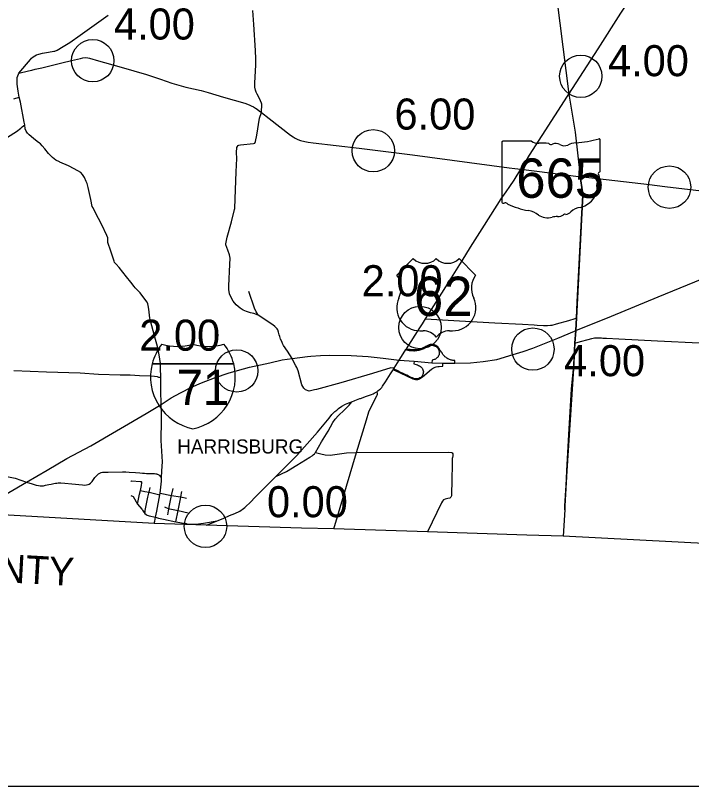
# Model space of a CAD drawing. Extents: x 1729596 to 1934326, y 644115 to 911751.
# Drawn here: x 1774831 to 1798753, y 650175 to 677476 of the extents above; entities that cross this region are included whole.
import ezdxf

# ---------------------------------------------------------------- set-up
doc = ezdxf.new("R2010")
doc.units = 0
for name, color, linetype in [('Default', 7, 'Continuous'), ('GM_X_Adjacent_County_Text', 7, 'Continuous'), ('GM_X_City_Street', 7, 'Continuous'), ('GM_X_Corporation_Text', 7, 'Continuous'), ('GM_X_County', 7, 'Continuous'), ('GM_X_County_Road', 7, 'Continuous'), ('GM_X_Interchange_Ramps', 7, 'Continuous'), ('GM_X_Interstate_Route', 7, 'Continuous'), ('GM_X_Interstate_Shield', 7, 'Continuous'), ('GM_X_State_Route', 7, 'Continuous'), ('GM_X_State_Shield', 7, 'Continuous'), ('GM_X_Township', 7, 'Continuous'), ('GM_X_Township_Road', 7, 'Continuous'), ('GM_X_US_Route', 7, 'Continuous'), ('GM_X_US_Shield', 7, 'Continuous'), ('SC_Scratch1', 7, 'Continuous')]:
    doc.layers.add(name, color=color, linetype=linetype)

msp = doc.modelspace()

# ---------------------------------------------------------------- linework, layer by layer
at = {"layer": 'Default'}
for centre in [(1777567, 675872), (1794833, 675322), (1787491, 672684), (1797971, 671396), (1789142, 666427), (1793139, 665662), (1782661, 664892), (1781555, 659388), (1781555, 659388)]:
    msp.add_circle(centre, 750, dxfattribs=at)
at = {"layer": 'GM_X_City_Street'}
for points in [[(1779847, 661240), (1779853, 661239), (1779883, 661223), (1779909, 661206), (1779930, 661187), (1779979, 661133), (1780000, 661107)], [(1778915, 660978), (1778930, 660991), (1778950, 660994), (1779248, 660981), (1779262, 660981), (1779284, 660976)], [(1779263, 660711), (1779287, 660836), (1779305, 660926), (1779302, 660952), (1779284, 660976)], [(1779741, 659492), (1779762, 659575), (1779789, 659710), (1779832, 659924), (1779945, 660504), (1779955, 660564), (1779994, 660984), (1779997, 661054)], [(1779147, 660174), (1779218, 660526), (1779253, 660654), (1779263, 660711)], [(1779551, 660558), (1779561, 660595), (1779563, 660601), (1779594, 660760)], [(1780218, 659794), (1780262, 660012), (1780354, 660480), (1780407, 660730)], [(1778914, 660484), (1778995, 660444), (1779147, 660174), (1779301, 659998), (1779316, 659981)], [(1779253, 660654), (1779413, 660623)], [(1779413, 660623), (1779561, 660595), (1779945, 660504)], [(1779413, 659848), (1779419, 659887), (1779421, 659949), (1779516, 660426), (1779551, 660558)], [(1779955, 660564), (1780354, 660480), (1780676, 660432)], [(1780676, 660432), (1780676, 660432), (1780681, 660430), (1780880, 660384)], [(1780679, 660419), (1780680, 660423), (1780681, 660430), (1780720, 660624)], [(1780506, 659550), (1780588, 659944), (1780679, 660419)], [(1779316, 659981), (1779328, 659966), (1779352, 659929), (1779378, 659888), (1779413, 659848)], [(1780101, 660073), (1780262, 660012), (1780292, 660006)], [(1780292, 660006), (1780588, 659944), (1780937, 659869)], [(1779413, 659848), (1779453, 659809), (1779488, 659785), (1779561, 659760), (1779789, 659710)], [(1779789, 659710), (1779892, 659678), (1780069, 659640), (1780506, 659550), (1780854, 659487), (1780872, 659483)]]:
    msp.add_lwpolyline(points, dxfattribs=at)
at = {"layer": 'GM_X_County'}
msp.add_lwpolyline([(1824608, 657476), (1824149, 657505), (1820365, 657774), (1819565, 657827), (1815551, 657995), (1815251, 658006), (1814713, 658027), (1811039, 658133), (1807036, 658278), (1802918, 658549), (1799575, 658756), (1799409, 658764), (1794213, 659039), (1792928, 659077), (1789408, 659196), (1786100, 659304), (1784956, 659328), (1781576, 659434), (1779741, 659492), (1773339, 659850)], dxfattribs=at)
at = {"layer": 'GM_X_County_Road'}
for points in [[(1784167, 666166), (1784139, 666268), (1784110, 666342), (1784086, 666380), (1784060, 666419), (1784007, 666466), (1783937, 666518), (1783844, 666582), (1783619, 666732), (1783419, 666860), (1783270, 666922), (1783149, 666951), (1783002, 666997), (1782890, 667046), (1782780, 667109), (1782641, 667230), (1782535, 667360), (1782467, 667486), (1782408, 667615), (1782384, 667769), (1782377, 667901), (1782412, 668652), (1782429, 668886), (1782404, 669000), (1782343, 669165), (1782281, 669354), (1782273, 669384), (1782325, 669630), (1782473, 670172), (1782582, 670601), (1782588, 670635), (1782611, 670984), (1782644, 671937), (1782659, 672414), (1782657, 672628), (1782664, 672804), (1782683, 672840), (1782701, 672870), (1782735, 672884), (1782799, 672895), (1783258, 672938), (1783298, 672959), (1783324, 673007), (1783374, 673235), (1783468, 673837), (1783535, 674036), (1783550, 674333), (1783542, 674374), (1783468, 674540), (1783387, 674689), (1783347, 674762), (1783328, 674832), (1783304, 674932), (1783299, 675075), (1783336, 675721), (1783338, 675938), (1783324, 676240), (1783261, 677156), (1783230, 677651)], [(1774956, 675429), (1775362, 675913), (1775404, 675965), (1775460, 676012), (1775514, 676048), (1775572, 676079), (1775656, 676108), (1775793, 676134), (1775936, 676163), (1776130, 676195), (1776187, 676207), (1776227, 676216), (1776304, 676244), (1776516, 676373), (1776754, 676520), (1777127, 676778), (1778110, 677485)], [(1775143, 673702), (1775006, 674406), (1774965, 674582)], [(1774127, 672717), (1774135, 672735), (1774225, 672873), (1774380, 673020), (1774555, 673162), (1774867, 673370), (1775024, 673487), (1775070, 673535), (1775162, 673604)], [(1776387, 672291), (1776262, 672357), (1776143, 672446), (1776006, 672587), (1775875, 672747), (1775780, 672854), (1775718, 672924), (1775682, 672955), (1775601, 673017), (1775473, 673119), (1775314, 673250), (1775264, 673305), (1775207, 673375), (1775170, 673458), (1775162, 673604), (1775143, 673702)], [(1779970, 664753), (1779970, 664754), (1779968, 664903), (1779958, 665156), (1779916, 665455), (1779856, 665754), (1779767, 666089), (1779704, 666310), (1779605, 666661), (1779588, 666760), (1779552, 667071), (1779533, 667201), (1779517, 667271), (1779492, 667327), (1779415, 667432), (1779242, 667654), (1779065, 667828), (1779034, 667876), (1778917, 668033), (1778760, 668219), (1778633, 668388), (1778498, 668548), (1778395, 668665), (1778341, 668727), (1778320, 668774), (1778204, 669129), (1778102, 669437), (1778095, 669601), (1778068, 669689), (1777883, 670067), (1777658, 670508), (1777579, 670661), (1777547, 670717), (1777497, 670964), (1777408, 671388), (1777367, 671520), (1777338, 671600), (1777278, 671733), (1777201, 671850), (1777142, 671913), (1776909, 672047), (1776709, 672149), (1776398, 672285), (1776389, 672290), (1776387, 672291)], [(1789344, 666734), (1790537, 666661), (1791789, 666590), (1792769, 666542), (1793180, 666519), (1793295, 666513)], [(1793295, 666513), (1793517, 666503), (1793658, 666499), (1793762, 666507), (1793824, 666510), (1793979, 666556), (1794410, 666679), (1794631, 666749)], [(1794631, 666749), (1794681, 666765)], [(1785488, 664237), (1785482, 664235), (1785415, 664217), (1785225, 664179), (1785099, 664218), (1785031, 664276), (1784960, 664401), (1784830, 664895), (1784787, 665008), (1784751, 665076), (1784708, 665153), (1784623, 665333), (1784452, 665588), (1784319, 665794), (1784282, 665863), (1784251, 665928), (1784214, 666014), (1784184, 666108), (1784167, 666166)], [(1794628, 665869), (1794828, 665926), (1795089, 666006), (1795229, 666043), (1795313, 666060), (1795373, 666064), (1795571, 666063), (1795618, 666051), (1795717, 666046), (1795747, 666045)], [(1795747, 666045), (1796176, 666025), (1797552, 665961), (1799023, 665886), (1800577, 665809), (1801360, 665776), (1801750, 665758), (1801954, 665741), (1802014, 665745), (1802050, 665761), (1802068, 665780), (1802080, 665822), (1802087, 665905)], [(1788230, 664988), (1788111, 664995), (1787461, 664802), (1786344, 664466), (1785488, 664237)], [(1779992, 662480), (1779997, 663084), (1779995, 663356), (1779983, 663706), (1779979, 664192), (1779975, 664462), (1779970, 664647), (1779970, 664753)], [(1786100, 659304), (1786899, 662007), (1787247, 663159), (1787335, 663439), (1787423, 663644), (1787619, 664011), (1787633, 664034), (1787638, 664068), (1787636, 664100), (1787627, 664132), (1787616, 664155)], [(1780000, 661107), (1780016, 661353), (1780029, 661677), (1779992, 662426), (1779992, 662464), (1779992, 662480)], [(1775570, 660850), (1775573, 660849), (1775645, 660831), (1775702, 660823), (1775752, 660820), (1775821, 660824), (1775899, 660840), (1776014, 660865), (1776093, 660882), (1776188, 660900), (1776247, 660912), (1776301, 660920), (1776345, 660924), (1776376, 660926), (1776437, 660926), (1776574, 660914), (1776830, 660891), (1777209, 660855), (1777290, 660850), (1777340, 660853), (1777402, 660866), (1777444, 660886), (1777493, 660920), (1777545, 660976), (1777644, 661113), (1777682, 661165), (1777719, 661203), (1777770, 661242), (1777821, 661270), (1777865, 661289), (1777912, 661301), (1777957, 661305), (1778112, 661307), (1778614, 661313), (1778735, 661315), (1778852, 661310), (1779083, 661293), (1779238, 661278), (1779326, 661271), (1779401, 661265), (1779473, 661263), (1779690, 661259), (1779718, 661258), (1779746, 661257)], [(1779746, 661257), (1779747, 661257), (1779794, 661251), (1779825, 661246), (1779847, 661240)], [(1774330, 661187), (1774345, 661182), (1774826, 661093), (1775224, 660950), (1775426, 660892), (1775570, 660850)], [(1779997, 661054), (1780000, 661107), (1780000, 661107)], [(1780872, 659483), (1780936, 659470), (1781001, 659463), (1781105, 659460), (1781183, 659463), (1781304, 659472), (1781396, 659484), (1781481, 659498), (1781967, 659586)]]:
    msp.add_lwpolyline(points, dxfattribs=at)
at = {"layer": 'GM_X_Interchange_Ramps'}
for points in [[(1788648, 665645), (1788671, 665631), (1788715, 665621), (1788758, 665616), (1788803, 665612), (1788844, 665609), (1788882, 665608), (1788922, 665607), (1788954, 665607), (1788993, 665609), (1789037, 665614), (1789079, 665620), (1789119, 665628), (1789156, 665637), (1789189, 665647), (1789224, 665659), (1789251, 665669), (1789283, 665685), (1789319, 665704), (1789351, 665720), (1789383, 665737), (1789442, 665769), (1789479, 665786), (1789526, 665797), (1789564, 665799), (1789607, 665796), (1789646, 665786), (1789687, 665769), (1789717, 665749), (1789749, 665723), (1789770, 665698), (1789790, 665668), (1789806, 665637), (1789817, 665605), (1789823, 665573), (1789825, 665540), (1789823, 665505), (1789818, 665476), (1789807, 665441), (1789792, 665410), (1789782, 665393), (1789762, 665367), (1789745, 665348), (1789722, 665329), (1789695, 665311), (1789673, 665299), (1789648, 665290), (1789574, 665271), (1789566, 665173)], [(1790378, 665161), (1790379, 665260), (1790311, 665265), (1790282, 665269), (1790252, 665275), (1790224, 665283), (1790191, 665294), (1790163, 665305), (1790126, 665324), (1790100, 665339), (1790077, 665355), (1790054, 665372), (1790029, 665394), (1790007, 665415), (1789996, 665428), (1789979, 665447), (1789957, 665476), (1789945, 665496), (1789925, 665526), (1789905, 665554), (1789885, 665584), (1789864, 665614), (1789839, 665651), (1789818, 665681), (1789799, 665709), (1789770, 665743), (1789743, 665767), (1789715, 665787), (1789676, 665806), (1789633, 665821), (1789593, 665827), (1789548, 665829), (1789508, 665824), (1789471, 665814), (1789442, 665802), (1789418, 665790), (1789380, 665769), (1789346, 665751), (1789313, 665734), (1789285, 665719), (1789253, 665703), (1789219, 665689), (1789185, 665677), (1789144, 665665), (1789113, 665658), (1789070, 665649), (1789024, 665642), (1788981, 665638), (1788940, 665637), (1788902, 665637), (1788866, 665638), (1788831, 665640), (1788795, 665643), (1788754, 665646), (1788716, 665651), (1788690, 665656), (1788666, 665672)], [(1788202, 664945), (1788246, 664917), (1788890, 664611), (1788940, 664593), (1788986, 664586), (1789026, 664585), (1789063, 664588), (1789100, 664597), (1789125, 664606), (1789168, 664630), (1789233, 664685), (1789547, 664951), (1789583, 664978), (1789623, 665001), (1789655, 665017), (1789680, 665026), (1789716, 665038), (1789771, 665048), (1789819, 665052), (1789947, 665059), (1789948, 665161)], [(1788936, 665236), (1788928, 665136), (1789009, 665119), (1789058, 665104), (1789096, 665087), (1789133, 665066), (1789166, 665041), (1789197, 665012), (1789217, 664990), (1789234, 664966), (1789249, 664931), (1789258, 664897), (1789263, 664860), (1789262, 664827), (1789257, 664795), (1789245, 664759), (1789233, 664734), (1789216, 664706), (1789197, 664683), (1789173, 664660), (1789144, 664640), (1789109, 664622), (1789070, 664611), (1789022, 664605), (1788971, 664608), (1788926, 664619), (1788876, 664641), (1788838, 664659), (1788782, 664685), (1788734, 664708), (1788674, 664737), (1788617, 664764), (1788570, 664786), (1788522, 664809), (1788461, 664838), (1788409, 664863), (1788356, 664888), (1788308, 664911), (1788255, 664936), (1788213, 664962)]]:
    msp.add_lwpolyline(points, dxfattribs=at)
at = {"layer": 'GM_X_Interstate_Route'}
for points in [[(1794609, 666298), (1794658, 666318), (1795918, 666832), (1797576, 667510), (1798866, 668046), (1800101, 668557), (1800602, 668805), (1800850, 668949), (1800959, 669021)], [(1788411, 665272), (1788936, 665236), (1789566, 665173), (1789948, 665161), (1790378, 665161), (1790931, 665174), (1791380, 665222), (1791866, 665300), (1792438, 665469), (1792800, 665575), (1793140, 665698), (1794026, 666055), (1794609, 666298)], [(1773339, 659850), (1775224, 660950), (1775957, 661376), (1776652, 661789), (1777498, 662236), (1779457, 663388), (1779983, 663706), (1780338, 663933), (1780676, 664112), (1781059, 664311), (1781412, 664474), (1781875, 664650), (1782399, 664828), (1783114, 665027), (1783830, 665175), (1784266, 665280), (1784623, 665333), (1785169, 665398), (1785278, 665407), (1785620, 665431), (1785943, 665448), (1786709, 665435), (1787312, 665395), (1787847, 665340), (1788411, 665272)]]:
    msp.add_lwpolyline(points, dxfattribs=at)
at = {"layer": 'GM_X_Interstate_Shield'}
for p, q in [((1779669, 665137), (1782554, 665137)), ((1782554, 665137), (1779669, 665137)), ((1782554, 665137), (1779669, 665137))]:
    msp.add_line(p, q, dxfattribs=at)
for centre, start, end in [((1781487, 664677), 141.669, 165.8066), ((1780564, 667633), 253.0091, 286.9909), ((1781659, 667633), 253.0091, 286.9909), ((1780737, 664677), 14.1934, 38.331), ((1781487, 664677), 165.8066, 258.463), ((1780737, 664677), 281.537, 14.1934)]:
    msp.add_arc(centre, 1875, start, end, dxfattribs=at)
at = {"layer": 'GM_X_State_Route'}
for points in [[(1776813, 675876), (1777131, 675954), (1777214, 675975), (1777318, 675984), (1777389, 675973), (1777453, 675960), (1777771, 675870), (1778493, 675666), (1779017, 675513)], [(1774779, 674519), (1774965, 674582), (1774929, 674798), (1774892, 675044), (1774891, 675067), (1774898, 675281), (1774939, 675401), (1774956, 675429), (1775298, 675511), (1775413, 675541), (1775530, 675569), (1775648, 675596), (1775766, 675623), (1775997, 675685), (1776236, 675741), (1776474, 675794), (1776813, 675876)], [(1779017, 675513), (1779470, 675381), (1779964, 675221), (1780368, 675082), (1780611, 675007), (1780865, 674940), (1781405, 674816), (1781645, 674748), (1782195, 674586), (1782945, 674365), (1783098, 674311), (1783174, 674276), (1783251, 674240), (1783326, 674193), (1783381, 674155), (1783451, 674103), (1783535, 674036), (1783804, 673822), (1784562, 673240), (1784654, 673177), (1784734, 673128), (1784820, 673089), (1784919, 673053), (1785066, 673017), (1785185, 672991), (1785368, 672966), (1786989, 672782), (1788878, 672539), (1792298, 672084), (1792500, 672057), (1792717, 672032)], [(1792717, 672032), (1793275, 671961), (1794757, 671777)], [(1794757, 671777), (1794806, 671771), (1797266, 671486), (1797804, 671424), (1799105, 671270), (1800498, 671103), (1801820, 670938), (1801979, 670920)]]:
    msp.add_lwpolyline(points, dxfattribs=at)
at = {"layer": 'GM_X_State_Shield'}
for p, q in [((1792042, 672983), (1792042, 670870)), ((1793095, 673019), (1792076, 673019)), ((1795522, 671966), (1795522, 673072)), ((1795522, 671967), (1795522, 671966))]:
    msp.add_line(p, q, dxfattribs=at)
for centre, major_axis, start_param, end_param in [((1792081, 672988), (40.3, 0), 1.712693, 3.28349), ((1793338, 673265), (391, 0), 4.042523, 4.731795), ((1794282, 675901), (3691, 0), 4.814394, 5.042369), ((1795483, 673076), (38.7, 0), 6.141152, 7.989035), ((1793467, 671833), (1404, 0), 1.404758, 1.657858), ((1793786, 672999), (113, 0), 3.836095, 5.185415), ((1793952, 672754), (235, 0), 0.950623, 2.079405), ((1794255, 673089), (282, 0), 4.081561, 5.145723), ((1794753, 672374), (743, 0), 1.699011, 2.107814), ((1795513, 671885), (60, 0), 1.883978, 3.671073), ((1795481, 671962), (41.5, 0), 5.05454, 6.418171), ((1795661, 671504), (262, 0), 2.387724, 3.262537), ((1795132, 671745), (360, 0), 5.934695, 6.695948), ((1794489, 671363), (923, 0), 5.101752, 6.440018), ((1792082, 670865), (40.7, 0), 3.00124, 4.508301), ((1792088, 671081), (310, 0), 4.665946, 4.897461), ((1792151, 670748), (112, 0), 0.519207, 1.627899), ((1793565, 672647), (2665, 0), 4.195997, 4.488961), ((1792770, 669920), (834, 0), 0.823519, 1.323587), ((1794878, 670277), (506, 0), 1.647645, 2.488434), ((1793672, 670737), (529, 0), 4.026481, 4.996735), ((1793978, 670007), (435, 0), 1.495662, 1.94098), ((1794016, 670579), (282, 0), 4.691044, 5.507374), ((1794271, 670374), (79.4, 0), 1.147584, 2.315152), ((1794238, 670665), (298, 0), 4.937069, 5.64225)]:
    msp.add_ellipse(centre, major_axis=major_axis, ratio=0.8, start_param=start_param, end_param=end_param, dxfattribs=at)
at = {"layer": 'GM_X_Township'}
msp.add_lwpolyline([(1793990, 678050), (1794416, 674693), (1794635, 673347), (1794806, 671771), (1794893, 671228), (1794908, 671097), (1794874, 670478), (1794681, 666765), (1794658, 666318), (1794628, 665869), (1794571, 664962), (1794341, 661348), (1794272, 660115), (1794265, 659967), (1794213, 659039)], dxfattribs=at)
at = {"layer": 'GM_X_Township_Road'}
for points in [[(1794711, 667339), (1794874, 670478), (1794908, 671097), (1794893, 671228), (1794806, 671771)], [(1783419, 666860), (1783397, 666917), (1783353, 666983), (1783295, 667108), (1783084, 667706)], [(1794628, 665869), (1794658, 666318), (1794681, 666765), (1794711, 667339)], [(1794594, 665324), (1794628, 665869)], [(1794312, 660830), (1794341, 661348), (1794413, 662634), (1794505, 664244), (1794571, 664962), (1794594, 665324)], [(1774772, 664906), (1775927, 664855), (1777126, 664825), (1777776, 664781), (1778534, 664755), (1778892, 664756), (1779224, 664731), (1779613, 664718), (1779753, 664707), (1779841, 664692), (1779897, 664671), (1779913, 664666), (1779970, 664647)], [(1784050, 661158), (1784421, 661328), (1784785, 661553), (1785245, 661832), (1785332, 661887), (1785362, 661915), (1785407, 661955), (1785429, 661979), (1785449, 662005), (1785660, 662374), (1785891, 662758), (1786065, 663060), (1786148, 663185), (1786257, 663311), (1786461, 663499), (1786634, 663678), (1786734, 663801)], [(1785449, 662005), (1785631, 661949), (1785794, 661914), (1785961, 661904), (1786544, 661990), (1786899, 662007), (1790170, 662010), (1790258, 661999), (1790282, 661987), (1790304, 661949), (1790304, 661888), (1790293, 661830), (1790285, 661792), (1790284, 661772)], [(1790284, 661772), (1790284, 661736), (1790282, 661618), (1790271, 661003), (1790262, 660542), (1790255, 660466), (1790233, 660426), (1790200, 660384), (1790128, 660371), (1790032, 660347), (1789976, 660322), (1789939, 660284), (1789905, 660222), (1789408, 659196)], [(1794265, 659967), (1794272, 660115), (1794312, 660830)]]:
    msp.add_lwpolyline(points, dxfattribs=at)
at = {"layer": 'GM_X_US_Route'}
for points in [[(1794369, 674621), (1794416, 674693), (1795452, 676291), (1796252, 677554), (1796540, 678009)], [(1792717, 672032), (1792863, 672264), (1793021, 672532), (1794369, 674621)], [(1790554, 668655), (1790636, 668785), (1790931, 669274), (1791427, 670046), (1792022, 670984), (1792196, 671234), (1792328, 671423), (1792474, 671646), (1792717, 672032)], [(1788666, 665672), (1789138, 666416), (1789230, 666553), (1789344, 666734), (1789553, 667059), (1789715, 667323), (1790257, 668184), (1790554, 668655)], [(1788490, 665396), (1788648, 665645), (1788666, 665672)], [(1788171, 664896), (1788202, 664945), (1788213, 664962), (1788230, 664988), (1788411, 665272), (1788490, 665396)], [(1787043, 663919), (1787255, 663998), (1787392, 664047), (1787427, 664059), (1787486, 664082), (1787528, 664103), (1787574, 664128), (1787616, 664155), (1787658, 664184), (1787715, 664230), (1787748, 664259), (1787789, 664303), (1787821, 664347), (1787928, 664501), (1788104, 664792), (1788171, 664896)], [(1782818, 659962), (1782858, 659989), (1782950, 660058), (1783174, 660262), (1783295, 660401), (1784050, 661158), (1784789, 661898), (1785521, 662721), (1785931, 663218), (1786031, 663343), (1786129, 663449), (1786199, 663506), (1786267, 663559), (1786382, 663639), (1786511, 663709), (1786630, 663762), (1786734, 663801), (1786844, 663844), (1787022, 663911), (1787043, 663919)], [(1782064, 659623), (1782208, 659678), (1782405, 659767), (1782588, 659843), (1782767, 659928), (1782818, 659962)], [(1781576, 659434), (1781708, 659481), (1781967, 659586), (1782064, 659623)]]:
    msp.add_lwpolyline(points, dxfattribs=at)
at = {"layer": 'GM_X_US_Shield'}
for p, q in [((1788908, 668865), (1788328, 668285)), ((1791112, 668285), (1790532, 668865)), ((1789140, 666313), (1789256, 666313)), ((1790184, 666313), (1790300, 666313))]:
    msp.add_line(p, q, dxfattribs=at)
for centre, radius, start, end in [((1789314, 669280), 580, 225.573, 314.427), ((1790126, 669280), 580, 225.573, 314.427), ((1787663, 667819), 812, 334.5471, 35.0009), ((1791778, 667819), 812, 144.9991, 205.4529), ((1789131, 667125), 812, 154.8319, 270.6383), ((1790309, 667125), 812, 269.3617, 25.1681), ((1789256, 665733), 580, 36.8699, 90), ((1790184, 665733), 580, 90, 143.1301)]:
    msp.add_arc(centre, radius, start, end, dxfattribs=at)
at = {"layer": 'SC_Scratch1'}
msp.add_lwpolyline([(1730291, 784675), (1926541, 784675), (1926541, 650175), (1730291, 650175)], close=True, dxfattribs=at)

# ---------------------------------------------------------------- texts
at = {"layer": 'Default'}
for s, p in [('4.00', (1778317, 676622)), ('4.00', (1795796, 675324)), ('6.00', (1788241, 673434)), ('2.00', (1787081, 667533)), ('2.00', (1779212, 665606)), ('4.00', (1794245, 664703)), ('0.00', (1783730, 659710))]:
    msp.add_text(s, height=1100, dxfattribs=at).set_placement(p)
at = {"layer": 'GM_X_Adjacent_County_Text'}
msp.add_text('PICKAWAY COUNTY', height=1000, rotation=356.8216, dxfattribs=at).set_placement((1763818, 657997))
at = {"layer": 'GM_X_Corporation_Text'}
msp.add_text('HARRISBURG', height=500, rotation=0, dxfattribs=at).set_placement((1780555, 661965))
at = {"layer": 'GM_X_Interstate_Shield'}
msp.add_text('71', height=1250, dxfattribs=at).set_placement((1780534, 663684))
at = {"layer": 'GM_X_State_Shield'}
msp.add_text('665', height=1392.2, dxfattribs=at).set_placement((1792552, 671019))
at = {"layer": 'GM_X_US_Shield'}
msp.add_text('62', height=1392.2, dxfattribs=at).set_placement((1788932, 666835))

doc.saveas('drawing.dxf')
